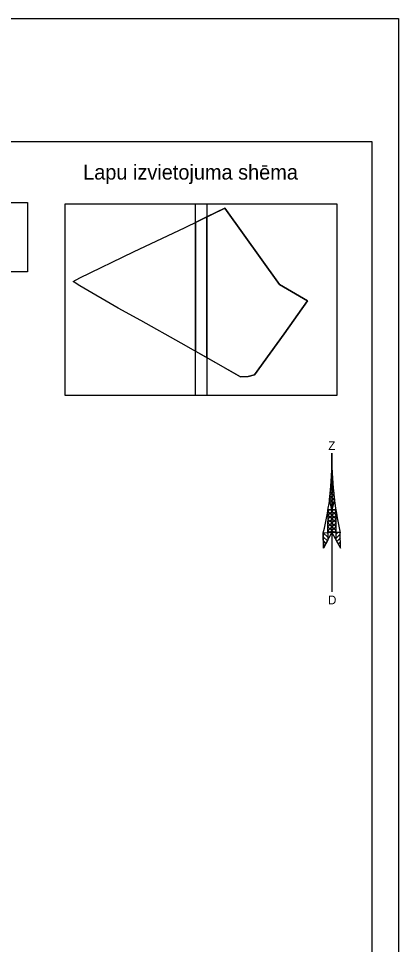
# Model space of a CAD drawing. Extents: x 619806 to 620082, y 405176 to 405386.
# Drawn here: x 620043.9 to 620082.2, y 405292.3 to 405385.6 of the extents above; entities that cross this region are included whole.
import ezdxf

# ---------------------------------------------------------------- set-up
doc = ezdxf.new("R2010")
doc.units = 0
doc.layers.add('RAMI_PLAN_####_TKST_#', color=7, linetype='Continuous')

msp = doc.modelspace()

# ---------------------------------------------------------------- linework, layer by layer
at = {"layer": 'RAMI_PLAN_####_TKST_#'}
for p, q in [((620062.876, 405365.609), (620061.725, 405365.047)), ((620061.725, 405365.047), (620061.725, 405352.091)), ((620062.876, 405365.609), (620062.876, 405351.438)), ((620062.876, 405351.438), (620062.876, 405365.609)), ((620061.725, 405352.091), (620062.876, 405351.438)), ((620062.876, 405351.438), (620066.27, 405349.512)), ((620075.474, 405341.793), (620075.474, 405327.823)), ((620075.451, 405339.7), (620075.515, 405339.759)), ((620075.454, 405339.723), (620075.518, 405339.662)), ((620075.477, 405340.092), (620075.499, 405340.07)), ((620075.406, 405338.883), (620075.552, 405339.016)), ((620075.414, 405338.982), (620075.567, 405338.841)), ((620075.432, 405339.291), (620075.533, 405339.39)), ((620075.434, 405339.355), (620075.542, 405339.252)), ((620075.288, 405337.605), (620075.643, 405337.941)), ((620075.322, 405337.908), (620075.676, 405337.572)), ((620075.338, 405338.038), (620075.612, 405338.3)), ((620075.358, 405338.264), (620075.637, 405337.996)), ((620075.373, 405338.463), (620075.581, 405338.659)), ((620075.386, 405338.624), (620075.604, 405338.418)), ((620075.24, 405337.167), (620075.675, 405337.582)), ((620075.243, 405337.209), (620075.657, 405336.812)), ((620075.282, 405337.558), (620075.725, 405337.134)), ((620075.301, 405336.836), (620075.716, 405337.236)), ((620075.087, 405335.562), (620075.687, 405336.132)), ((620075.091, 405335.953), (620075.277, 405336.132)), ((620075.091, 405335.94), (620075.874, 405335.196)), ((620075.298, 405336.132), (620075.874, 405335.584)), ((620075.32, 405336.747), (620075.577, 405336.5)), ((620075.373, 405336.519), (620075.649, 405336.782)), ((620075.435, 405336.245), (620075.495, 405336.189)), ((620075.446, 405336.201), (620075.517, 405336.271)), ((620075.706, 405336.132), (620075.871, 405335.974)), ((620075.076, 405334.385), (620075.874, 405335.147)), ((620075.081, 405334.779), (620075.874, 405335.534)), ((620075.084, 405335.172), (620075.871, 405335.92)), ((620075.084, 405335.172), (620075.875, 405334.418)), ((620075.087, 405335.553), (620075.875, 405334.807)), ((620075.072, 405333.994), (620075.875, 405334.757)), ((620075.076, 405334.402), (620075.702, 405333.807)), ((620075.081, 405334.785), (620075.877, 405334.028)), ((620075.283, 405333.807), (620075.875, 405334.369)), ((620074.603, 405333.773), (620074.626, 405332.225)), ((620074.607, 405333.773), (620075.07, 405333.337)), ((620074.609, 405333.383), (620075.037, 405332.981)), ((620074.626, 405332.225), (620075.487, 405333.798)), ((620074.985, 405333.803), (620075.071, 405333.721)), ((620075.072, 405334.014), (620075.292, 405333.807)), ((620075.487, 405333.798), (620076.344, 405332.225)), ((620075.689, 405333.807), (620075.877, 405333.984)), ((620075.875, 405333.226), (620076.325, 405333.652)), ((620075.877, 405333.613), (620076.074, 405333.803)), ((620075.964, 405332.918), (620076.329, 405333.27)), ((620076.344, 405332.225), (620076.322, 405333.798)), ((620074.614, 405332.99), (620074.898, 405332.724)), ((620074.621, 405332.594), (620074.758, 405332.466)), ((620074.626, 405332.232), (620074.635, 405332.24)), ((620076.103, 405332.666), (620076.333, 405332.884)), ((620076.242, 405332.411), (620076.34, 405332.501)), ((620076.344, 405332.227), (620076.344, 405332.227))]:
    msp.add_line(p, q, dxfattribs=at)
for points in [[(619933.685, 405385.595), (620082.185, 405385.595), (620082.185, 405175.595), (619933.685, 405175.595)], [(619936.885, 405180.095), (619936.885, 405373.209), (620079.485, 405373.209), (620079.485, 405180.095)], [(620011.491, 405367.059), (620044.835, 405367.059), (620044.835, 405360.072), (620011.491, 405360.072)], [(620048.616, 405347.606), (620048.616, 405366.917), (620062.876, 405366.917), (620062.876, 405347.606)], [(620061.725, 405347.606), (620061.725, 405366.917), (620075.985, 405366.917), (620075.985, 405347.606)], [(620055.506, 405362.094), (620060.709, 405364.551), (620064.704, 405366.501), (620070.211, 405358.8), (620073.007, 405357.144), (620070.656, 405353.825), (620069.251, 405351.888), (620067.697, 405349.689), (620067.036, 405349.514), (620066.27, 405349.512), (620060.304, 405352.898), (620056.25, 405355.172), (620053.945, 405356.402), (620050.101, 405358.668), (620049.411, 405359.117), (620050.101, 405359.472)], [(620075.473, 405336.092), (620075.233, 405337.124), (620075.343, 405338.079), (620075.413, 405338.953), (620075.475, 405340.092), (620075.496, 405340.092), (620075.552, 405339.016), (620075.668, 405337.648), (620075.73, 405337.099)], [(620075.092, 405336.132), (620075.871, 405336.132), (620075.877, 405333.805), (620075.071, 405333.81)], [(620075.071, 405333.81), (620075.069, 405333.035), (620074.626, 405332.225), (620074.603, 405333.773)], [(620075.877, 405333.805), (620075.875, 405333.075), (620076.344, 405332.225), (620076.322, 405333.798)]]:
    msp.add_lwpolyline(points, close=True, dxfattribs=at)
msp.add_lwpolyline([(620066.27, 405349.512), (620067.036, 405349.514), (620067.697, 405349.689), (620069.251, 405351.888), (620070.656, 405353.825), (620073.007, 405357.144), (620070.211, 405358.8), (620064.704, 405366.501), (620062.876, 405365.609)], dxfattribs=at)
for centre, major_axis, start_param, end_param in [((620043.141, 405340.909), (32.345, 0), 6.048896, 6.311872), ((620113.811, 405341.426), (-38.341, 0), 6.273156, 6.494161)]:
    msp.add_ellipse(centre, major_axis=major_axis, ratio=0.950423, start_param=start_param, end_param=end_param, dxfattribs=at)

# ---------------------------------------------------------------- texts
for s, height, p in [('Lapu izvietojuma shēma', 1.5, (620050.425, 405369.368)), ('Z', 0.878, (620075.119, 405342.134)), ('D', 0.878, (620075.085, 405326.58))]:
    msp.add_text(s, height=height, rotation=360, dxfattribs=at).set_placement(p)

doc.saveas('drawing.dxf')
